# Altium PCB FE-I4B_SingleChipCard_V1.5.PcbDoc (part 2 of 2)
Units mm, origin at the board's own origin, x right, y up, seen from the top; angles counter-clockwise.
Board outline 100 x 100 mm, 5 copper layers (Top Layer, pad layer, GND, power, Bottom Layer); 136 components, 118 nets, 544 pads, 176 vias.
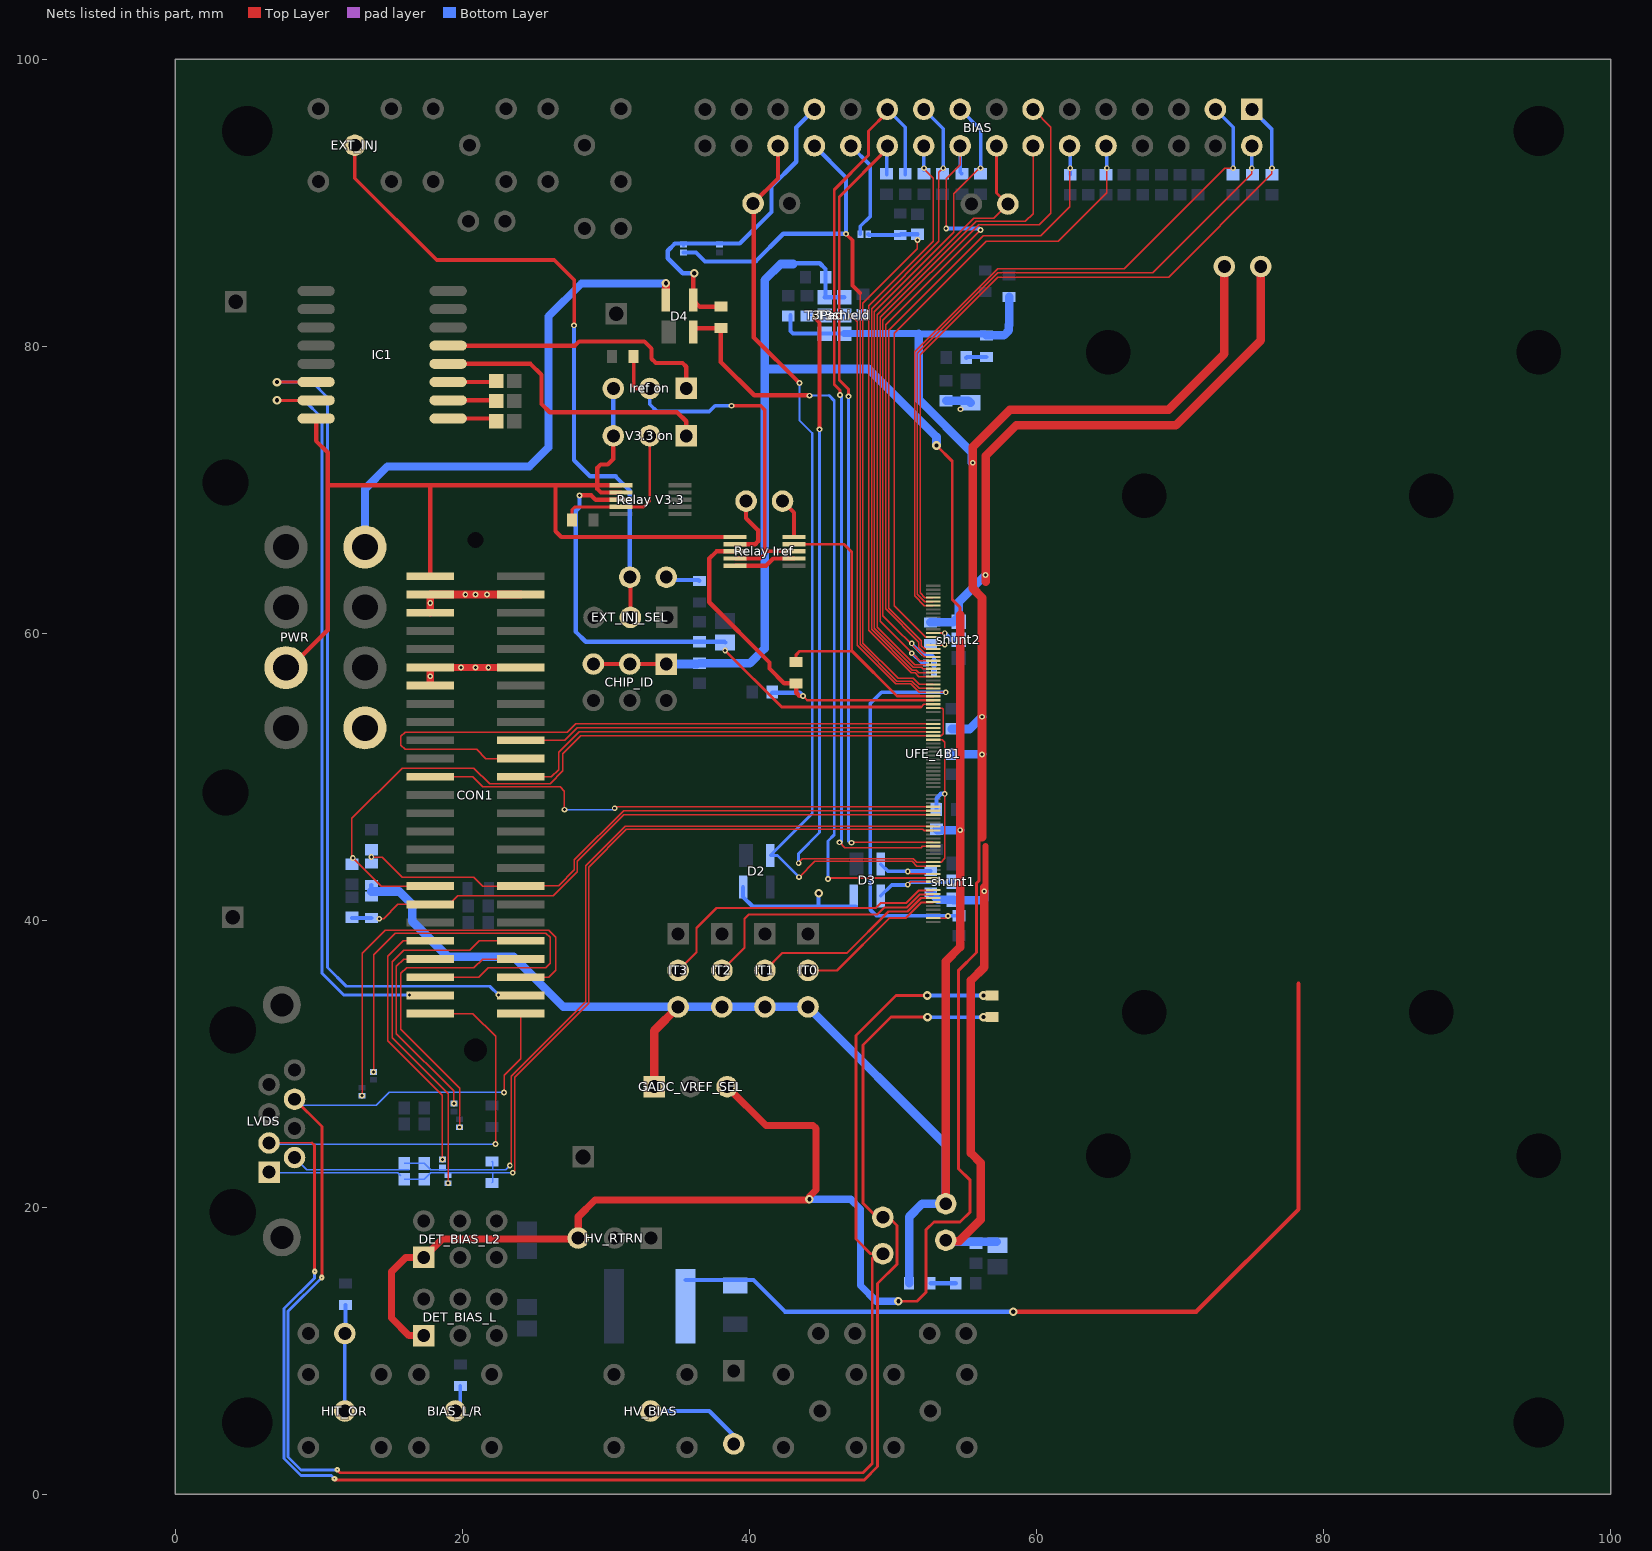
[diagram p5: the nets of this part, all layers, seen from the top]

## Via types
v1: diameter 0.4, hole 0.2, Top Layer to Bottom Layer, 157 vias
v2: diameter 0.6, hole 0.3, Top Layer to Bottom Layer, 13 vias
v3: diameter 0.4, hole 0.102, Top Layer to Bottom Layer, 4 vias
v4: diameter 0.25, hole 0, Top Layer to Bottom Layer, 2 vias

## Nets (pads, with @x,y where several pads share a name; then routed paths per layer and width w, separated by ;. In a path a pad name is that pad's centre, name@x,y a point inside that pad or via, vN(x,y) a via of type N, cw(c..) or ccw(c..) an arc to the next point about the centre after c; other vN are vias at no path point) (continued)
IREFEN: "Iref on.2" "Relay Iref.4" "Relay Iref.8" R22.2 | length 27.1
  Top Layer w0.254: R22.2@31.925,79.275 31.925,77.2 32.075,77.05 33.05,77.05 ; v1(38.75,75.85) 40.775,75.85 41.05,75.575 41.05,65.7 ; 39,65.2 40.75,65.2 41.05,65.5 41.05,65.7 ; 43.1,65.7 41.05,65.7
  Bottom Layer w0.254: 33.05,77.05 33.05,75.95 33.55,75.45 37.2,75.45 37.6,75.85 v1(38.75,75.85)
IREFON: "Iref on.1" IC1.5 | length 19.4
  Top Layer w0.3: IC1.5@19,80.035 27.835,80.035 28.125,80.325 32.675,80.325 33.175,79.825 33.175,79.125 33.475,78.825 35.325,78.825 35.59,78.56 35.59,77.05
IREFOUT: "Relay Iref.9" sj3.1 UFE_4B1.29 | length 22.6
  Top Layer w0.15: 51.8,55.6 UFE_4B1.29@52.8,55.6
  Top Layer w0.2: 43.1,66.2 46.575,66.2 47.125,65.65 47.125,58.775 50.275,55.625 51.825,55.625 ; sj3.1@43.25,58 43.25,58.5 43.49,58.74 43.735,58.74 47.11,58.74
IREFTUNE0: IT0.2 UFE_4B1.125 | length 10.7
  Top Layer w0.15: IT0.2@44.075,36.5 46.1,36.5 49.76,40.16 50.902,40.16 51.982,41.24 52.765,41.24 UFE_4B1.125@52.8,41.275
IREFTUNE1: IT1.2 UFE_4B1.124 | length 13.8
  Top Layer w0.15: IT1.2@41.075,36.5 42.3,37.725 46.8,37.725 49.685,40.61 51.013,40.61 51.953,41.55 UFE_4B1.124@52.8,41.55
IREFTUNE2: IT2.2 UFE_4B1.123 | length 18.1
  Top Layer w0.15: IT2.2@38.075,36.5 39.65,38.075 39.65,40.1 39.95,40.4 48.9,40.4 49.387,40.888 50.951,40.888 51.854,41.79 52.765,41.79 UFE_4B1.123@52.8,41.825
IREFTUNE3: IT3.2 UFE_4B1.122 | length 21.1
  Top Layer w0.15: IT3.2@35.025,36.5 36.3,37.775 36.3,39.45 37.7,40.85 48.8,40.85 49.15,41.2 50.924,41.2 51.789,42.065 52.765,42.065 UFE_4B1.122@52.8,42.1
LVDSDRVIREF: BIAS.19 C42.1 UFE_4B1.17 | length 44.5
  Top Layer w0.1: UFE_4B1.17@52.8,57.25 51.8,57.25 51.63,57.42 51.342,57.42 48.5,60.262 48.5,82.6 53.2,87.3 53.2,92.1 v1(53.5,92.4)
  Bottom Layer w0.25: BIAS.19@52.14,96.5 53.5,95.14 C42.1@53.5,92.3
LVDSDRVVOS: BIAS.20 C57.1 UFE_4B1.18 | length 42
  Top Layer w0.1: v1(52.15,92.4) 52.15,92.35 52.8,91.7 52.8,87.3 48.3,82.8 48.3,60.194 51.264,57.23 51.551,57.23 51.806,56.975 UFE_4B1.18@52.8,56.975
  Bottom Layer w0.25: BIAS.20@52.14,93.96 52.15,93.95 52.15,92.25 52.2,92.3 C57.1@52.15,92.35
LVDSRECVBN: BIAS.22 C59.1 UFE_4B1.94 | length 57.9
  Top Layer w0.1: v1(47.1,45.4) 47.125,45.425 UFE_4B1.94@52.8,45.425 ; BIAS.22@49.6,93.75 BIAS.22@49.6,93.96
  Top Layer w0.2: v1(46.9,76.5) 46.9,77 46.25,77.65 46.25,90.4 BIAS.22@49.6,93.75
  Bottom Layer w0.2: 46.9,45.5 v1(46.9,76.5)
  Bottom Layer w0.25: C59.1@49.55,91.95 49.55,93.91 BIAS.22@49.6,93.96
LVDSRECVBP: BIAS.21 C44.1 UFE_4B1.95 | length 64.7
  Top Layer w0.1: v1(46.275,45.425) 46.635,45.065 46.954,45.065 46.959,45.06 47.241,45.06 47.246,45.065 51.965,45.065 52.05,45.15 UFE_4B1.95@52.8,45.15 ; BIAS.21@49.6,96.3 BIAS.21@49.6,96.5
  Top Layer w0.2: v1(46.3,76.6) 46.3,76.925 45.9,77.325 45.9,90.9 48.3,93.3 48.3,95 BIAS.21@49.6,96.3
  Bottom Layer w0.2: v1(46.275,45.425) 46.325,45.425 46.4,45.5 46.4,76.5 v1(46.3,76.6)
  Bottom Layer w0.25: BIAS.21@49.6,96.5 50.85,95.25 C44.1@50.85,91.95
NC1: "Relay Iref.5" "Relay Iref.7" | length 4.3
  Top Layer w0.3: 39,64.7 41.15,64.7 41.65,65.2 43.1,65.2
NetBIAS_L/R_1: BIAS_L/R.1 R1.1 | length 1.9
  Bottom Layer w0.254: BIAS_L/R.1@19.5,5.8 19.85,6.15 R1.1@19.85,7.55
NetCON1_41: CON1.41 JP2.2 | length 19.1
  Top Layer w0.1: CON1.41@17.75,38.565 15.865,38.565 14.8,37.5 14.8,31.6 18.6,27.8 v1(18.6,23.325)
NetCON1_42: CON1.42 JP1.2 | length 26.6
  Top Layer w0.1: v1(19,21.675) 19,27.9 15.1,31.8 15.1,37.1 15.9,37.9 20.5,37.9 21.165,38.565 CON1.42@24.05,38.565
NetCON1_43: CON1.43 JP4.2 | length 13.9
  Top Layer w0.1: CON1.43@17.75,37.295 15.895,37.295 15.4,36.8 15.4,32.1 19.4,28.1 19.4,27.3 v1@19.3,27.2
  other v1: 19.4,27.225
NetCON1_44: CON1.44 JP3.2 | length 21.2
  Top Layer w0.1: v1@19.7,25.575 19.8,25.675 19.8,28.3 15.7,32.4 15.7,36.3 16.1,36.7 20.8,36.7 21.395,37.295 CON1.44@24.05,37.295
  other v1: 19.8,25.575
NetCON1_45: CON1.45 JP6.2 | length 31.8
  Top Layer w0.1: v1(13.8,29.425) 13.8,37.6 15.3,39.1 25.8,39.1 26.1,38.8 26.1,37 25.8,36.7 21.8,36.7 21.125,36.025 CON1.45@17.75,36.025
NetCON1_46: CON1.46 JP5.2 | length 29.2
  Top Layer w0.1: v1(13,27.775) 13,37.7 14.6,39.3 26,39.3 26.5,38.8 26.5,36.5 26.025,36.025 CON1.46@24.05,36.025
NetCR1_1: CR1.1 RR1.1 | length 1.8
  Bottom Layer w0.3: RR1.1@52.625,14.7 CR1.1@54.375,14.7
NetCR2_1: CR2.1 RR2.1 | length 1.4
  Bottom Layer w0.3: CR2.1@55.1,79.2 55.15,79.25 RR2.1@56.5,79.25
NetEXT_INJ_1: EXT_INJ.1 EXT_INJ_SEL.2 JPterm.2 | length 46.5
  Top Layer w0.254: EXT_INJ.1@12.5,94 12.5,91.7 18.2,86 26.4,86 27.775,84.625 v1(27.775,81.45)
  Top Layer w0.3: JPterm.2@31.66,63.7 31.7,63.66 EXT_INJ_SEL.2@31.7,61.1
  Bottom Layer w0.3: v1@27.775,81.475 v1(27.775,81.45) 27.775,72.05 28.9,70.925 30.67,70.925 31.66,69.935 JPterm.2@31.66,63.9
NetHIT_OR_1: HIT_OR.1 HitOr.1 R11.1 | length 7.4
  Top Layer w0.254: HitOr.1@11.8,11.2 HitOr.1@11.85,11.25
  Bottom Layer w0.254: HIT_OR.1@11.8,5.8 HitOr.1@11.8,11.2 ; HitOr.1@11.85,11.25 R11.1@11.85,13.2
NetHV_BIAS_1: HV_BIAS.1 sHV.3 | length 7.8
  Bottom Layer w0.3: HV_BIAS.1@33.1,5.8 37.2,5.8 sHV.3@38.9,4.1 ; sHV.3@38.9,4.1 39,4 39,3.61 sHV.3@38.9,3.51 sHV.3@38.9,4.1
NetIC1_1: IC1.1 P1.2 | length 3.4
  Top Layer w0.3: IC1.1@19,74.955 22.179,74.955 P1.2@22.361,74.773
NetIC1_2: IC1.2 P2.2 | length 3.4
  Top Layer w0.3: IC1.2@19,76.225 22.309,76.225 P2.2@22.361,76.173
NetIC1_3: IC1.3 P3.2 | length 3.4
  Top Layer w0.3: IC1.3@19,77.495 22.283,77.495 P3.2@22.361,77.573
NetIref_1: "Relay Iref.10" Iref.1 | length 2.8
  Top Layer w0.3: Iref.1@42.3,69.2 43.1,68.4 43.1,66.7
NetIref_2: "Relay Iref.2" Iref.2 | length 4.8
  Top Layer w0.3: 39,66.2 40.4,66.2 40.6,66.4 40.6,67.17 39.76,68.01 Iref.2@39.76,69.2
NetJPterm_1: JPterm.1 R5.2 | length 2.4
  Bottom Layer w0.1: R5.2@36.45,63.7 R5.2@36.5,63.65
  Bottom Layer w0.3: JPterm.1@34.2,63.7 36.45,63.7 R5.2@36.5,63.65
NetR21_2: "Relay V3.3.4" "V3.3 on.2" R21.2 | length 10.9
  Top Layer w0.2: R21.2@27.625,67.875 27.625,68.6 27.825,68.8 31.05,68.8 32.625,68.8 33.05,69.225 33.05,73.75
NTC1: CON1.49 EXT_NTC.1 LVDS.3 NTC.2 | length 137.4
  Top Layer w0.1: LVDS.3@6.52,24.476 9.524,24.476 ; CON1.49@17.75,33.485 20.715,33.485 22.3,31.9 v1(22.3,24.4)
  Top Layer w0.2: 9.524,24.476 9.7,24.3 v3(9.7,15.525) ; v3@11.075,1 48,1 48.925,1.925 48.925,14.675 50.275,16.025 50.275,18.725 49.7,19.3 48.875,19.3 47.9,20.275 47.9,31.3 49.85,33.25 v2(52.4,33.25)
  Bottom Layer w0.1: LVDS.3@6.52,24.476 6.596,24.4 v1(22.3,24.4)
  Bottom Layer w0.2: v3(9.7,15.525) 9.7,15.075 7.56,12.935 7.56,2.48 8.74,1.3 10.85,1.3 v3(11.075,1.075)
  Bottom Layer w0.25: v2(52.4,33.25) v2(56.3,33.25)
NTC2: CON1.50 EXT_NTC.2 LVDS.6 NTC.1 | length 130.1
  Top Layer w0.1: v1(22.9,28) 22.9,29.2 24.05,30.35 CON1.50@24.05,33.485
  Top Layer w0.2: LVDS.6@8.298,27.524 10.2,25.622 v3(10.2,15.1) ; v3(11.275,1.7) 11.475,1.5 47.9,1.5 48.55,2.15 48.55,16.435 48.875,16.76 48.44,16.76 47.425,17.775 47.425,31.975 50.2,34.75 v2(52.375,34.75)
  Bottom Layer w0.1: LVDS.6@8.298,27.524 8.722,27.1 14,27.1 14.9,28 v1(22.9,28)
  Bottom Layer w0.2: v3(10.2,15.1) 7.85,12.75 7.85,2.6 8.75,1.7 v3(11.275,1.7)
  Bottom Layer w0.25: v2(52.375,34.75) v2(56.3,34.75)
PLLIBIAS: BIAS.18 C41.1 UFE_4B1.14 | length 44.7
  Top Layer w0.1: UFE_4B1.14@52.8,58.625 52.175,58.625 51.785,59.015 51.785,59.378 49.513,61.65 49.5,61.65 49.5,81.5 v1(56.1,88.1) ; v1(53.7,88.2) 53.7,91.65 54.68,92.63 BIAS.18@54.68,93.96
  pad layer w0.1: v1(53.7,88.2) v1@53.8,88.1
  Bottom Layer w0.25: v1(53.7,88.2) 56,88.2 v1(56.1,88.1) ; BIAS.18@54.68,93.96 54.68,92.12 C41.1@54.8,92
PLLICP: BIAS.17 C56.1 UFE_4B1.16 | length 45.2
  Top Layer w0.1: UFE_4B1.16@52.8,57.525 52.075,57.525 51.99,57.61 51.421,57.61 48.7,60.331 48.7,82.4 54.225,87.925 54.225,90.625 v1@56.1,92.5
  Bottom Layer w0.25: BIAS.17@54.68,96.5 56.1,95.08 v1(56.1,92.4)
PRMPVBNFOL: BIAS.3 C49.1 UFE_4B1.4 | length 50.7
  Top Layer w0.1: UFE_4B1.4@52.8,61.925 52.175,61.925 51.5,62.6 51.5,79.6 57.3,85.4 66.1,85.4 73.1,92.4 v1(73.7,92.4)
  Bottom Layer w0.25: BIAS.3@72.46,96.5 73.7,95.26 v1(73.7,92.4)
PRMPVBNLCC: BIAS.2 C34.1 UFE_4B1.3 | length 48.5
  Top Layer w0.1: UFE_4B1.3@52.8,62.2 52.2,62.2 51.7,62.7 51.7,79.5 57.3,85.1 68.1,85.1 75,92 v1(75,92.4)
  Bottom Layer w0.25: v1(75,92.4) BIAS.2@75,93.96
PRMPVBP: BIAS.12 C35.1 UFE_4B1.13 | length 44.6
  Top Layer w0.1: UFE_4B1.13@52.8,58.9 52.2,58.9 51.975,59.125 51.975,59.456 49.7,61.731 49.7,81.1 51.7,83.1 56.3,87.7 60.3,87.7 62.3,89.7 v1@62.3,92.3 ; BIAS.12@62.3,93.96 BIAS.12@62.35,93.91
  Bottom Layer w0.25: C35.1@62.35,91.95 BIAS.12@62.35,93.91
  other v1: 62.35,92.4
PRMPVBPF: BIAS.1 C48.1 UFE_4B1.2 | length 52.4
  Top Layer w0.1: UFE_4B1.2@52.8,62.475 52.225,62.475 51.9,62.8 51.9,79.4 57.3,84.8 69.2,84.8 76.4,92 v1(76.4,92.4)
  Bottom Layer w0.25: BIAS.1@75,96.5 76.4,95.1 v1(76.4,92.4)
RABAR1: C46.1 CON1.35 UFE_4B1.41 UFE_4B1.52 | length 56.7
  Top Layer w0.1: CON1.35@17.75,42.375 14.325,42.375 v1(12.359,44.341) 12.3,44.4 12.3,47.1 15.8,50.6 20.8,50.6 21.9,49.5 26.1,49.5 27,50.4 27,51.6 28.25,52.85 UFE_4B1.52@52.8,52.85 53.35,52.85 53.5,53 53.5,54.7 53.425,54.775 UFE_4B1.41@52.8,54.775
RD1BAR: C45.1 CON1.36 R12.1 UFE_4B1.84 | length 42.6
  Top Layer w0.1: v1(13.65,44.4) 14.4,44.4 15.8,43 20.8,43 21.425,42.375 CON1.36@24.05,42.375 24.05,42.4 26.7,42.4 27.8,43.5 27.8,44.2 31.225,47.625 UFE_4B1.84@52.8,47.625
RD2BAR: CD45.1 CON1.37 RD12.1 UFE_4B1.85 | length 43.4
  Top Layer w0.1: v1(14.2,40.1) 14.5,40.1 15.505,41.105 CON1.37@17.75,41.105 19.08,41.105 19.675,41.7 26.325,41.7 28,43.375 28,44.1 31.25,47.35 UFE_4B1.85@52.8,47.35
  Bottom Layer w0.3: CD45.1@12.3,40.15 RD12.1@13.65,40.15
REFCLKN: C6.1 C6.2 JP2.1 LVDS.2 R9.2 UFE_4B1.88 | length 65.1
  Top Layer w0.1: v1@23.4,23 23.4,29.125 28.6,34.325 28.6,43.8 31.35,46.55 UFE_4B1.88@52.775,46.55
  Top Layer w0.12: v1(23.3,22.9) v1@23.4,23 ; UFE_4B1.88@52.775,46.55 UFE_4B1.88@52.8,46.525
  Bottom Layer w0.1: LVDS.2@8.298,23.46 9.158,22.6 16.3,22.6 ; C6.2@15.95,23.05 C6.1@17.35,23.05 17.8,22.6 22.1,22.6 ; R9.2@22.05,23.2 22.1,23.15 22.1,22.6 ; v1(23.3,22.9) 23,22.6 22.1,22.6
REFCLKP: C7.1 C7.2 JP1.1 LVDS.1 R9.1 UFE_4B1.89 | length 66.3
  Top Layer w0.1: 23.65,22.55 23.65,29.05 28.8,34.2 28.8,43.7 31.425,46.325 52.075,46.325 52.1,46.3
  Top Layer w0.12: v1(23.5,22.4) 23.65,22.55 ; 52.1,46.3 52.15,46.25 UFE_4B1.89@52.8,46.25
  Bottom Layer w0.1: LVDS.1@6.52,22.4 15.5,22.4 C7.1@15.7,22.2 ; C7.1@15.95,21.95 C7.2@17.35,21.95 17.8,22.4 22.1,22.4 ; R9.1@22.05,21.7 22.1,21.75 22.1,22.4 ; v1(23.5,22.4) 22.1,22.4
REG1IN: C19.1 C20.1 CON1.3 CON1.4 CON1.5 D2.4 D3.4 D4.4 Digital.1 PWR.7 Rext1.1 shunt1.1 | length 92.9
  Top Layer w0.4: v1@56.45,42.1 56.45,45.175
  Top Layer w0.55: CON1.5@17.75,61.425 CON1.3@17.75,62.695 v1(20.2,62.695) v1(20.9,62.695) v1(21.7,62.695) CON1.4@24.05,62.695 ; D4.4@34.175,83.2 v2(34.175,84.375)
  Top Layer w0.6: Digital.1@53.65,17.625 54.6,17.625 56.1,19.125 56.1,23.1 55.425,23.775 55.425,35.8 56.35,36.725 56.35,42.3
  Bottom Layer w0.3: D2.4@39.55,42.3 39.55,41.625 40.225,40.95 44.8,40.95 ; v2(44.825,41.875) 44.8,41.85 44.8,40.95 ; D3.4@47.4,40.95 44.8,40.95
  Bottom Layer w0.55: PWR.7@13.2,66 13.2,70.05 14.775,71.625 24.675,71.625 26,72.95 26,82.075 28.3,84.375 v2(34.175,84.375)
  Bottom Layer w0.6: Rext1.1@52.625,41.925 53.125,41.425 shunt1.1@54.225,41.425 ; Digital.1@53.675,17.7 53.775,17.6 C19.1@57.225,17.6 ; shunt1.1@54.2,41.4 56.35,41.4 56.35,42.011 v1(56.352,42.013)
  other v1: 17.75,62.1
REG1OUT: C26.1 C27.1 C28.1 CHIP_ID.1 CHIP_ID.3 CHIP_ID.5 Digital.2 GADC_VREF_SEL.1 IT0.3 IT1.3 IT2.3 IT3.3 R12.2 RD12.2 RR1.2 T3Pad.3 T3shield.3 | length 182.3
  Top Layer w0.2: v2(53.025,73.075) 54.125,71.975 54.125,62.35 54.675,61.8 54.675,61.275
  Top Layer w0.3: CHIP_ID.5@29.12,57.85 CHIP_ID.3@31.66,57.85 CHIP_ID.1@34.2,57.85
  Top Layer w0.6: GADC_VREF_SEL.1@33.36,28.4 33.36,32.295 IT3.3@35.025,33.96 ; Digital.2@53.675,20.24 53.675,37.125 54.675,38.125 v1(54.675,46.275) 54.675,61.275
  Bottom Layer w0.2: T3Pad.3@45.25,83.405 T3Pad.3@45.3,83.455
  Bottom Layer w0.3: RD12.2@13.65,42 R12.2@13.65,42.45 ; 43.225,85.775 44.9,85.775 45.3,85.375 C27.1@45.3,84.8 T3Pad.3@45.3,83.455 ; T3Pad.3@45.25,83.405 T3shield.3@46.6,83.405
  Bottom Layer w0.6: RD12.2@13.65,42 15.6,42 16.5,41.1 16.5,39.925 18.975,37.45 23.55,37.45 27.04,33.96 IT3.3@35.025,33.96 IT2.3@38.075,33.96 IT1.3@41.075,33.96 IT0.3@44.075,33.96 53.675,24.36 Digital.2@53.675,20.24 52.025,20.24 51.125,19.34 RR1.2@51.125,14.7 ; CHIP_ID.1@34.2,57.85 C28.1@36.322,57.85 ; C28.1@36.5,57.9 40.025,57.9 41.05,58.925 41.05,78.404 ; 43.05,85.725 42.175,85.725 41.05,84.6 41.05,78.404 ; v2@53.025,73.175 53.025,73.675 48.296,78.404 41.05,78.404 ; C26.1@53.05,46.325 53.1,46.275 v1(54.675,46.275)
REG2IN: Analog.1 C17.1 C18.1 CON1.11 CON1.12 CON1.13 PWR.1 Rext2.1 shunt2.1 | length 52
  Top Layer w0.5: CON1.13@17.75,56.345 CON1.11@17.75,57.615 CON1.12@24.05,57.615
  Top Layer w0.6: 56.45,63.575 v1(56.45,64.05) 56.45,72.35 58.575,74.475 69.7,74.475 75.625,80.4 Analog.1@75.625,85.55 Analog.1@75.413,85.338
  Bottom Layer w0.6: Rext2.1@52.6,60.75 54.2,60.75 shunt2.1@54.412,60.962 ; C18.1@53.7,76.2 55.25,76.2 C17.1@55.4,76.05 ; shunt2.1@54.575,60.8 54.575,62.175 v1(56.45,64.05)
  other v1: 17.75,57 19.9,57.615 20.9,57.615 21.8,57.615 54.7,75.6
REG2OUT: Analog.2 C31.1 C32.1 C33.1 DET_BIAS_L2.1 DET_BIAS_L.1 GADC_VREF_SEL.3 HV_RTRN.3 R2.2 RR2.2 T3Pad.1 T3shield.1 | length 188.2
  Top Layer w0.2: v2(50.375,13.45) 51.675,13.45 52.303,14.078 52.303,18.428 52.85,18.975 54.675,18.975 55.375,19.675 55.375,21.875 54.55,22.7 54.55,36.475 55.825,37.75 55.825,42.575 56,42.75 56,46.254
  Top Layer w0.5: DET_BIAS_L.1@17.3,11.05 16.275,11.05 15.05,12.275 15.05,15.5 16.05,16.5 DET_BIAS_L2.1@17.3,16.5 18.575,17.775 27.985,17.775 HV_RTRN.3@28.06,17.85 28.06,19.335 29.225,20.5 44.125,20.5 v2(44.175,20.55) ; GADC_VREF_SEL.3@38.44,28.4 41.145,25.695 44.433,25.695 44.632,25.496 44.632,21.208 v2@44.175,20.751
  Top Layer w0.6: 56.2,45.8 v1(56.2,51.55) v1(56.2,54.175) 56.2,62.475 55.55,63.125 v1(55.55,71.875) 55.55,72.975 58.15,75.575 69.2,75.575 73.085,79.46 Analog.2@73.085,85.55
  Bottom Layer w0.3: C33.1@42.85,82.15 42.85,81.05 43.025,80.875 T3Pad.1@45.25,80.875 T3shield.1@46.6,80.875
  Bottom Layer w0.5: v2(44.175,20.55) 47.05,20.55 47.725,19.875 47.725,14.55 48.825,13.45 v2(50.375,13.45) ; T3shield.1@46.6,80.875 51.825,80.875 ; 51.8,80.85 56.4,80.85 RR2.2@56.5,80.75 ; 58.075,81.475 58.1,81.45
  Bottom Layer w0.6: 51.8,80.85 51.8,76.275 55.5,72.575 v1@55.5,71.875 ; C31.1@54.1,53.325 55.35,53.325 v1(56.2,54.175) v1@56.175,54.2 ; C32.1@54.125,51.575 54.15,51.55 v1(56.2,51.55) ; RR2.2@56.5,80.75 57.725,80.75 58.075,81.1 58.075,81.475 ; 58.1,81.45 R2.2@58.1,83.45
REGABDACLD: CON1.20 UFE_4B1.48 | length 29.1
  Top Layer w0.1: CON1.20@24.05,52.535 27.135,52.535 28,53.4 UFE_4B1.48@52.8,53.4
REGABSTBLD: CON1.22 UFE_4B1.47 | length 46.9
  Top Layer w0.1: CON1.22@24.05,51.15 CON1.22@24.05,51.265 21.635,51.265 21,51.9 16,51.9 15.7,52.2 15.7,52.8 16,53.1 27.3,53.1 27.875,53.675 UFE_4B1.47@52.8,53.675
REXT1: D3.2 Rext1.2 UFE_4B1.116 | length 5.5
  Top Layer w0.1: v1(51.025,43.4) 51.2,43.225 UFE_4B1.116@52.8,43.225
  Bottom Layer w0.25: D3.2@49.15,43.9 49.65,43.4 v1(51.025,43.4) 51.05,43.425 Rext1.2@52.625,43.425
REXT2: Rext2.2 UFE_4B1.7b | length 1.7
  Top Layer w0.1: UFE_4B1.7b@52.8,59.175 53.5,59.175 v1@53.5,59.2
  Bottom Layer w0.1: Rext2.2@52.6,59.25 52.65,59.2 v1(53.6,59.2)
SCL: CON1.48 IC1.14 | length 59.2
  Top Layer w0.2: v2(7.075,77.495) IC1.14@9.8,77.495 ; IC1.14@10.6,77.5 10.69,77.5 IC1.14@10.695,77.495
  Bottom Layer w0.2: v2(7.075,77.495) 9.53,77.495 10.6,76.425 10.6,36.7 11.9,35.4 21.9,35.4 v1(22.5,34.8)
SDA: CON1.47 IC1.15 | length 51.8
  Top Layer w0.2: v2(7.075,76.225) IC1.15@9.8,76.225
  Bottom Layer w0.2: v2(7.075,76.225) 8.975,76.225 10.2,75 10.2,36.3 11.7,34.8 v1(16.3,34.8)
SELALTBUS: CON1.24 UFE_4B1.49 | length 30.7
  Top Layer w0.1: CON1.24@24.05,49.995 26.195,49.995 26.7,50.5 26.7,51.7 28.125,53.125 UFE_4B1.49@52.8,53.125
SELCMD: CON1.23 UFE_4B1.81 | length 36.7
  Top Layer w0.1: CON1.23@17.75,49.995 20.705,49.995 21.4,49.3 26.8,49.3 27.1,49 v1@27.1,47.8 ; v1(30.6,47.8) 30.7,47.9 UFE_4B1.81@52.8,47.9
  Bottom Layer w0.1: v1(27.1,47.7) 30.5,47.7 v1(30.6,47.8)
SENSOR: C3.1 R3.2 | length 62.3
  Top Layer w0.3: v2(58.375,12.725) 71.125,12.725 78.25,19.85 78.25,35.575
  Bottom Layer w0.3: C3.1@35.55,14.925 40.275,14.925 42.475,12.725 v2(58.375,12.725)
TDACVBP: BIAS.10 C38.1 UFE_4B1.11 | length 44.6
  Top Layer w0.1: UFE_4B1.11@52.8,59.725 52.275,59.725 50.1,61.9 50.1,80.9 56.5,87.3 61.5,87.3 64.9,90.7 v1@64.9,92.3
  Bottom Layer w0.25: BIAS.10@64.84,93.96 64.9,93.9 v1(64.9,92.4)
V3.3IN: "Iref on.3" "Relay Iref.1" "Relay V3.3.1" "Relay V3.3.2" "V3.3 on.3" CON1.1 IC1.16 PWR.4 | length 71.2
  Top Layer w0.3: PWR.4@7.7,57.6 8,57.6 10.6,60.2 10.6,70.3 ; IC1.16@9.8,74.955 9.8,73.4 10.6,72.6 10.6,70.3 ; CON1.1@17.75,63.965 17.75,70.25 ; 26.475,70.3 26.475,67.1 26.875,66.7 39,66.7 ; 30.51,73.75 30.51,72.135 30.125,71.75 29.625,71.75 29.4,71.525 29.4,70.3 ; 31.05,69.8 29.65,69.8 29.4,70.05 29.4,70.3 ; 31.05,70.3 29.4,70.3 ; 10.6,70.3 29.4,70.3
  Bottom Layer w0.3: 30.51,73.75 30.51,77.05
V3.3ON: "V3.3 on.1" IC1.4 | length 20.4
  Top Layer w0.3: IC1.4@19,78.765 24.735,78.765 25.5,78 25.5,75.975 26.075,75.4 34.95,75.4 35.59,74.76 35.59,73.75
VBBNIN: "Relay Iref.3" C43.1 sj3.2 UFE_4B1.30 | length 26.4
  Top Layer w0.15: v1(43.725,55.625) 44.025,55.325 UFE_4B1.30@52.8,55.325
  Top Layer w0.3: 39,65.7 37.7,65.7 37.2,65.2 37.2,62.15 41.388,57.962 41.388,57.537 42.425,56.5 sj3.2@43.25,56.5 43.25,55.85 43.475,55.625 v1(43.725,55.625)
  Bottom Layer w0.3: C43.1@41.575,55.85 43.5,55.85 v1(43.725,55.625)
VBP1: BIAS.28 D2.2 mreg1.1 UFE_4B1.114 | length 65.8
  Top Layer w0.1: v1(43.45,43) 44.55,44.1 51.329,44.1 51.654,43.775 UFE_4B1.114@52.8,43.775
  Top Layer w0.15: mreg1.1@40.05,89.975 mreg1.1@40.3,89.725
  Top Layer w0.3: mreg1.1@40.25,89.95 41.98,91.68 BIAS.28@41.98,93.96 ; mreg1.1@40.3,89.725 40.3,80.6 v1(43.475,77.425)
  Bottom Layer w0.15: v1(43.475,77.425) 43.475,74.825 44.375,73.925
  Bottom Layer w0.2: v1(43.45,43) 41.95,44.5 D2.2@41.45,44.5 44.375,47.425 44.375,73.925
VBP2: BIAS.16 mreg2.1 UFE_4B1.9b | length 43.4
  Top Layer w0.1: UFE_4B1.9b@52.8,57.8 51.5,57.8 48.9,60.4 48.9,82.2 55.625,88.925 57.025,88.925 mreg2.1@58,89.9
  Top Layer w0.2: BIAS.16@57.22,93.96 57.22,90.68 mreg2.1@58,89.9
VDD33: "Relay V3.3.3" C13.1 C14.1 UFE_4B1.37 | length 39.6
  Top Layer w0.1: 51.95,54.85 52.15,55.05 UFE_4B1.37@52.8,55.05
  Top Layer w0.2: v1(38.3,58.8) 42.25,54.85 51.95,54.85
  Top Layer w0.3: v1(28.15,69.6) 28.975,69.6 29.275,69.3 31.05,69.3
  Bottom Layer w0.3: v1(28.15,69.6) 28.15,68.775 27.9,68.525 27.9,60.09 28.59,59.4 C13.1@36.5,59.4 38.25,59.4 C14.1@38.3,59.35
VDDDSHUNT1: D3.3 shunt1.2 UFE_4B1.118 | length 7.3
  Top Layer w0.1: v1(51.025,42.475) 51.225,42.675 UFE_4B1.118@52.8,42.675
  Bottom Layer w0.25: D3.3@49.15,41.7 49.9,42.45 51,42.45 v1(51.025,42.475) 51.2,42.65 54.19,42.65 shunt1.2@54.225,42.685
VDDDSHUNT2: shunt2.2 UFE_4B1.6b | length 1.9
  Top Layer w0.15: UFE_4B1.6b@52.8,60 v1@53.5,60
  Bottom Layer w0.3: v1(53.6,60) 54.06,59.54 shunt2.2@54.575,59.54
VDDT3PAD: C9.1 C10.1 T3Pad.2 UFE_4B1.59 UFE_4B1.105 | length 61
  Top Layer w0.1: v1@43.425,44.05 43.665,44.29 51.408,44.29 51.648,44.05 UFE_4B1.105@52.8,44.05 53.35,44.05 53.6,44.3 v1@53.6,48.802 ; UFE_4B1.59@52.8,52.575 53.425,52.575 53.6,52.4 v1@53.6,48.802 ; v1@53.575,48.8 53.577,48.802 v1@53.6,48.802 ; v1(53.603,48.802) v1@53.6,48.802
  Top Layer w0.25: v1(44.6,82.135) 44.6,81.9 44.875,81.625 v1(44.875,74.2)
  Bottom Layer w0.1: C9.1@44.015,82.135 T3Pad.2@45.25,82.135
  Bottom Layer w0.2: v1(43.425,43.975) 43.425,44.65 44.875,46.1 v1@44.875,74.1
  Bottom Layer w0.3: C10.1@53.025,47.725 53.025,48.5 53.327,48.802 v1(53.603,48.802)
VDDT3SHIELD: C11.1 C12.1 T3shield.2 UFE_4B1.28 UFE_4B1.134 | length 59.8
  Top Layer w0.1: v1(47.1,82.1) 47.5,81.7 47.5,59.163 50.193,56.47 51.237,56.47 51.832,55.875 v1(53.675,55.875) ; UFE_4B1.134@52.8,40.15 53.675,40.15 v1(53.825,40.3)
  Bottom Layer w0.1: T3shield.2@46.635,82.1 v1(47.1,82.1) ; C12.1@47.835,82.135 C12.1@47.9,82.2
  Bottom Layer w0.25: v1(53.675,55.875) 49.2,55.875 48.4,55.075 48.4,40.75 48.85,40.3 v1(53.825,40.3) 54.575,40.3 C11.1@54.6,40.325
  Bottom Layer w0.3: T3shield.2@46.6,82.135 C12.1@47.835,82.135
VREF1: D4.2 Resd.1 UFE_4B1.117 | length 54.3
  Top Layer w0.1: v1@45.475,42.85 v1@45.575,42.95
  Top Layer w0.15: v1@45.575,42.95 UFE_4B1.117@52.8,42.95
  Top Layer w0.3: D4.2@36.075,81 36.325,81.25 Resd.1@38.025,81.25 ; Resd.1@38,81.25 38,78.9 40.325,76.575 44.175,76.575 v1(44.175,76.55)
  Bottom Layer w0.15: v1(44.175,76.55) 45.55,76.55
  Bottom Layer w0.2: v1(45.475,42.875) 45.475,45.525 45.9,45.95 45.9,76.2 45.55,76.55
VREF1_IN: BIAS.25 D4.3 Resd.2 sj21.1 sj115.1 | length 25.1
  Top Layer w0.1: BIAS.25@44.52,96.5 BIAS.25@44.9,96.5
  Top Layer w0.3: v2(36.15,85.075) 36.075,85 D4.3@36.075,83.2 36.525,82.75 Resd.2@38.025,82.75 ; Resd.2@38,82.75 Resd.2@38.025,82.775
  Bottom Layer w0.1: BIAS.25@44.52,96.08 BIAS.25@44.52,96.5 ; BIAS.25@44.7,96.5 BIAS.25@44.52,96.5 ; BIAS.25@44.9,96.5 BIAS.25@44.52,96.5
  Bottom Layer w0.3: sj21.1@35.4,87.075 sj21.1@35.325,87.15 ; v2(36.15,85.075) 35.35,85.075 34.3,86.125 34.3,86.65 34.8,87.15 sj21.1@35.325,87.15 ; BIAS.25@44.52,96.5 43.25,95.23 43.25,92.85 41.525,91.125 41.525,89.35 39.325,87.15 sj21.1@35.325,87.15
VREF2: BIAS.13 sj15.1 sj19.1 UFE_4B1.8b | length 50.8
  Top Layer w0.1: UFE_4B1.8b@52.8,58.35 52.175,58.35 49.3,61.225 49.3,81.8 55.975,88.475 60.2,88.475 61,89.275 61,95.26 BIAS.13@59.76,96.5
  Bottom Layer w0.25: v1(51.308,59.292) 51.308,59.258 52.045,58.522 52.662,58.522 52.853,58.331 sj15.1@52.853,57.912 sj19.1@52.853,57.25
VREFOUTAN: BIAS.14 sj15.2 UFE_4B1.15 | length 46.3
  Top Layer w0.1: UFE_4B1.15@52.8,58.075 51.85,58.075 49.1,60.825 49.1,82 55.8,88.7 59.225,88.7 59.76,89.235 BIAS.14@59.76,93.96
  Bottom Layer w0.2: v1(51.308,58.597) 51.993,57.912 sj15.2@52.303,57.912
  Bottom Layer w0.25: BIAS.14@59.325,93.525 BIAS.14@59.76,93.96
VREFOUTDIG: BIAS.26 sj21.2 UFE_4B1.21 | length 54.8
  Top Layer w0.1: v1(46.725,87.825) v1@46.75,87.8 ; 47.7,83.7 47.7,59.231 50.271,56.66 51.315,56.66 51.825,56.15 UFE_4B1.21@52.8,56.15
  Top Layer w0.25: v1@46.75,87.8 47.175,87.375 47.175,84.225 47.7,83.7
  Bottom Layer w0.3: sj21.2@35.4,86.525 36.275,86.525 36.9,85.9 40.425,85.9 42.35,87.825 v1@46.675,87.825 ; BIAS.26@44.52,93.96 46.725,91.755 v1(46.725,87.825)
VTHEXT: BIAS.24 VTH_EXT.2 | length 7
  Bottom Layer w0.25: BIAS.24@47.06,93.96 48.398,92.622 48.398,89.023 47.725,88.35 VTH_EXT.2@47.725,87.8
VTHINC: C55.1 R4.1 UFE_4B1.20 VTH_EXT.1 | length 39.4
  Top Layer w0.1: v1@51.7,87.5 51.7,86.8 47.9,83 47.9,59.3 50.35,56.85 51.394,56.85 51.819,56.425 UFE_4B1.20@52.8,56.425
  Bottom Layer w0.1: R4.1@50.5,87.75 R4.1@50.5,87.85
  Bottom Layer w0.3: VTH_EXT.1@48.275,87.8 48.325,87.75 R4.1@50.5,87.75 ; R4.1@50.55,87.8 C55.1@51.7,87.8
  other v1: 51.7,87.4
pads on no net: "Relay V3.3.7" "Relay V3.3.8" "Relay V3.3.9" "Relay V3.3.10" BIAS.4 BIAS.23 CON1.2 CON1.6 CON1.14 CON1.81 CON1.82 IC1.6 IC1.7 IC1.9 IC1.10 IC1.11 IC1.12 IC1.13 LVDS.MH3 LVDS.MH4 PWR.3 PWR.5 PWR.6 PWR.9 PWR.10
copper on no net: | length 611.9
  pad layer w0.01: 52.8,39.875 58.327,40.281
  pad layer w0.02: 52.775,45.425 58,46.712 ; 52.8,40.15 58,40.45 ; 52.8,40.45 58.327,40.664 ; 52.8,40.725 58,41.5 ; 52.8,41 58,41.65 ; 52.8,41.275 58,41.8 ; 52.8,41.55 58,41.95 ; 52.8,41.825 58,42.1 ; 52.8,42.1 58,42.25 ; 52.8,42.675 58,43.3 ; 52.8,42.95 58,43.45 ; 52.8,43.225 58,43.588 ; 52.8,43.5 58,43.688 ; 52.8,43.775 58,43.788 ; 52.8,44.05 58,45.125 ; 52.8,44.325 58,45.725 ; 52.8,44.6 58,45.875 ; 52.8,44.875 58,46.025 ; 52.8,45.15 58,46.612 ; 52.8,45.7 58,47.15 ; 52.8,45.975 58,47.3 ; 52.8,46.25 58,47.45 ; 52.8,46.5 58,47.6 ; 52.8,46.8 58,47.75 ; 52.8,47.075 58,47.9 ; 52.8,47.35 58,48.05 ; 52.8,47.625 58,48.2 ; 52.8,47.9 58,48.65 ; 52.8,48.175 58,48.8 ; 52.8,48.45 58,48.95 ; 52.8,48.725 58,49.1 ; 52.8,49.275 58,49.85 ; 52.8,49.55 58,50 ; 52.8,49.825 58,50.15 ; 52.8,50.1 58,50.3 ; 52.8,50.375 58,50.45 ; 52.8,50.65 58,50.6 ; 52.8,50.925 58,50.75 ; 52.8,51.2 58,50.9 ; 52.8,51.75 58,51.175 ; 52.8,52.025 58,51.325 ; 52.8,52.3 58,51.475 ; 52.8,52.575 58,51.925 ; 52.8,52.85 58,52.975 ; 52.8,53.125 58,53.425 ; 52.8,53.4 58,53.575 ; 52.8,53.675 58,53.725 ; 52.8,53.95 58,53.875 ; 52.8,54.5 58,54.475 ; 52.8,54.775 58,54.625 ; 52.8,55.05 58,55.225 ; 52.8,55.325 58,56.275 ; 52.8,55.6 52.775,55.575 58,56.425 ; 52.8,55.875 58,56.575 ; 52.8,56.15 58,57.633 ; 52.8,56.425 58,57.783 ; 52.8,56.7 58,57.933 ; 52.8,56.975 58,58.083 ; 52.8,57.25 58,58.233 ; 52.8,57.525 58,58.383 ; 52.8,57.8 58.298,58.46 ; 52.8,58.075 58,58.533 ; 52.8,58.35 58.298,58.61 ; 52.8,58.625 58,58.67 ; 52.8,58.9 58,58.77 ; 52.8,59.175 58.298,58.76 ; 52.8,59.45 58,58.87 ; 52.8,59.725 58,58.97 ; 52.8,60 58.298,58.91 ; 52.8,60.275 58,59.07 ; 52.8,60.55 58,59.17 ; 52.8,60.825 58,59.27 ; 52.8,61.1 58,59.37 ; 52.8,61.375 58,59.47 ; 52.8,61.65 58,59.57 ; 52.8,61.925 58,59.67 ; 52.8,62.2 58,59.77 ; 52.8,62.475 58,59.87 ; 52.8,62.75 58,60 ; 52.8,63.025 58.327,59.941 ; 52.8,63.3 58.327,60.169 ; 52.825,51.475 58,51.037 ; 54.675,40.914 58,40.9 ; 54.675,44.801 58,45.575 ; 54.675,46.172 58,47 ; 54.675,48.125 58,48.5 ; 54.675,49.45 58,49.7 ; 54.675,52.125 58,51.775 ; 54.675,52.423 58,52.375 ; 54.675,54.261 58,54.325 ; 54.675,55.605 58,55.525 ; 54.675,56.525 58,57.025 ; 54.7,49.175 58,49.4 ; 55.25,40.425 58,40.6 ; 55.25,40.775 58,40.75 ; 55.425,44.025 58,44.075 ; 55.425,46.325 58,46.85 ; 55.425,48.1 58,48.35 ; 55.425,49.075 58,49.25 ; 55.425,49.375 58,49.55 ; 55.425,51.975 58,51.625 ; 55.425,53.125 58,53.125 ; 55.425,54.05 58,54.025 ; 55.425,54.95 58,54.775 ; 55.425,55.813 55.426,55.813 ; 55.425,57.875 58.298,58.31 ; 55.65,41.05 58,41.05 ; 56.2,43.875 58,43.925 ; 56.2,44.225 58,44.225 ; 56.2,45.925 58,46.175 ; 56.2,52.575 58,52.525 ; 56.2,53.225 58,53.275 ; 56.2,54.175 58,54.175 ; 56.2,55.725 56.2,55.675 58,55.675 ; 56.2,55.825 58,55.975 ; 56.2,57 58,57.175 ; 58,41.2 55.25,41.092 58,41.35 ; 58,44.375 55.425,44.45 ; 58,44.525 55.425,44.45 ; 58,44.675 54.675,44.388 58,44.975 ; 58,44.825 55.425,44.45 ; 58,45.275 56.456,45.05 55.425,44.9 58,45.425 ; 58,46.325 55.425,45.875 58,46.475 ; 58,52.075 55.425,52.35 58,52.225 ; 58,52.675 55.425,52.775 58,52.825 ; 58,54.925 56.2,55.125 58,55.075 ; 58,55.375 55.425,55.825 55.522,55.825 ; 58,55.825 55.522,55.825 ; 58,56.125 55.522,55.825 ; 58,56.725 55.425,56.6 58,56.875 ; 58,57.325 55.471,56.911 58,57.475
  pad layer w0.1: 54.675,42.682 58,42.775 ; 55.425,42.95 58,43.075 ; 55.425,62.225 58.298,59.135 ; 56.2,61.7 58.298,59.435 ; 56.325,42.4 58,42.475 ; 56.6,63.4 58.298,59.735
  other v4: 52.8,38.875 52.8,64.3

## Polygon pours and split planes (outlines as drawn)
GND on GND (split plane): 78.74,82.55 60.96,82.55 60.96,64.77 56.896,64.77 56.896,38.1 60.96,38.1 60.96,0.51 0.51,0.51 0.51,99.49 78.74,99.49
REG1IN on power (split plane): 54.873,62.525 54.881,62.486 54.903,62.453 54.936,62.431 54.975,62.423 56.896,62.423 56.896,38.1 60.96,38.1 60.96,0.61 28.952,0.61 28.952,59.5 28.944,59.539 28.922,59.572 28.889,59.594 28.85,59.602 10.525,59.602 10.525,68.873 54.873,68.873
REG2IN on power (split plane): 78.74,82.55 60.96,82.55 60.96,64.77 56.896,64.77 56.896,62.627 55.077,62.627 55.077,68.975 55.069,69.014 55.047,69.047 55.014,69.069 54.975,69.077 10.423,69.077 10.384,69.069 10.351,69.047 10.329,69.014 10.322,68.975 10.322,59.5 10.329,59.461 10.351,59.428 10.384,59.406 10.423,59.398 28.748,59.398 28.748,0.51 0.51,0.51 0.51,99.49 78.74,99.49

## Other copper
Top Layer:
  rectangle net SENSOR: 77.7,35.6 78.8,37.1
  rectangle net GND: 19.45,53.8 22.475,55.07
  rectangle net GND: 19.35,58.885 22.375,60.155
  text "58/60" at 59.7,58.3 h2
  text "STFC FE-I4B SCC V1.5" at 65.808,5.034 h2
  text "NOV 2015" at 65.808,3.384 h2
GND (plane layer: these items are gaps in the copper):
  pour cut-out: 56.896,38.1 60.96,38.1 60.96,-0.254 100.33,-0.254 100.35,38.275 100.35,64.875 100.33,100.33 78.74,100.33 78.74,82.55 60.96,82.55 60.96,64.77 56.896,64.77
  pour cut-out: 37.63,4.8 40.13,4.8 40.13,2.3 37.63,2.3
  pour cut-out: 31.8,7 34.3,7 34.3,4.5 31.8,4.5
  pour cut-out: 37,10.45 41,10.45 41,6.35 37,6.35
power (plane layer: these items are gaps in the copper):
  pour cut-out: 56.896,38.1 60.96,38.1 60.96,-0.254 100.33,-0.254 100.35,38.275 100.35,64.875 100.33,100.33 78.74,100.33 78.74,82.55 60.96,82.55 60.96,64.77 56.896,64.77
  pour cut-out: 31.8,7.025 34.3,7.025 34.3,4.525 31.8,4.525
  pour cut-out: 37.63,4.825 40.13,4.825 40.13,2.325 37.63,2.325
  pour cut-out: 36.975,10.425 40.975,10.425 40.975,6.325 36.975,6.325
  lines w0.2: 10.423,59.5 28.85,59.5 28.85,0.508 99.1,0.508 99.1,62.525 54.975,62.525 54.975,68.975 10.423,68.975 10.423,59.5

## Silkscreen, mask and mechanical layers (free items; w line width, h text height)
Top Overlay:
  circle w0.254: c85.215,88.925 r0.5
  circle w0.254: c82.715,88.925 r0.5
  circle w0.254: c80.175,88.925 r0.5
  circle w0.254: c80.175,85.7 r0.5
  circle w0.254: c82.715,85.7 r0.5
  circle w0.254: c85.215,85.65 r0.5
  circle w0.254: c80.2,82.425 r0.5
  circle w0.254: c82.74,82.425 r0.5
  circle w0.254: c85.24,82.375 r0.5
  rectangle: 79.3,84.75 83.5,86.55
  rectangle: 81.925,81.45 86.125,83.25
  lines w0.127: 15.525,88.7 16.9,90.075
  lines w0.2: 67.5,29.675 67.5,33.575 ; 67.5,30.875 87.5,30.875 ; 87.5,29.7 87.5,33.6 ; 87.5,33.575 91.5,33.575 ; 87.5,69.575 91.5,69.575 ; 90.25,33.575 90.25,69.575
  lines w0.254: 78.865,84.45 78.865,86.92 86.465,86.92 86.465,84.41 78.905,84.41 ; 78.865,87.725 78.865,90.195 86.465,90.195 86.465,87.685 78.905,87.685 ; 78.89,81.175 78.89,83.645 86.49,83.645 86.49,81.135 78.93,81.135 ; 78.35,76.725 78.35,91.3 98.275,91.3 98.275,76.725 78.35,76.725
  text "OFF" at 87.3,88.275 h1
  text "ON" at 87.35,85 h1
  text "I2C Control" at 87.15,82.25 h1
  text "Iref on" at 79.45,79.1 h1
  text "V3.3 on" at 79.4,77.425 h1
  text "36.0mm" at 92.825,48.5 h1.52 r90
  text "Connect the UV Pads with" at 79,41.5 h2 r90
  text "flying wire" at 80.875,41.45 h2 r90
  text "20.0mm" at 73.35,28.65 h1.52
Top Solder:
  rectangle: 52.15,35.975 57.15,65.5
  rectangle: 53.371,39.268 54.571,63.318
  rectangle: 77.663,35.6 78.838,37.1
Mechanical 1:
  lines w0.1: 0,0 22.2,0 100,0 100,100 0,100 0,0
Mechanical 2:
  lines w0.6: 57.3,45.648 57.3,38.7 62.45,38.7 ; 57.3,47.1 57.3,51.15 ; 57.3,52.6 57.3,56.65 ; 57.3,58.302 57.3,64.45 62.45,64.45 ; 64.2,64.45 70.6,64.45 ; 64.3,38.7 70.7,38.7 ; 72.2,64.45 78.6,64.45 ; 72.3,38.7 78.7,38.7 ; 80.2,64.45 86.6,64.45 ; 80.3,38.7 86.7,38.7 ; 88.2,64.45 94.6,64.45 ; 88.3,38.7 94.7,38.7 ; 96.2,64.45 100,64.45 100,58.302 ; 96.3,38.7 100,38.7 100,45.648 ; 100,47.1 100,51.15 ; 100,52.6 100,56.65
Mechanical 28:
  circle w0.013: c65,79.575 r1.5
  circle w0.013: c65,79.575 r1.25
  circle w0.013: c95,79.575 r1.5
  circle w0.013: c95,79.575 r1.25
  circle w0.013: c65,23.575 r1.5
  circle w0.013: c65,23.575 r1.25
  circle w0.013: c95,23.575 r1.5
  circle w0.013: c95,23.575 r1.25
  circle w0.013: c95,5 r1.5
  circle w0.013: c95,5 r1.25
  circle w0.013: c5,5 r1.5
  circle w0.013: c5,5 r1.25
  circle w0.013: c5,95 r1.5
  circle w0.013: c5,95 r1.25
  circle w0.013: c95,95 r1.5
  circle w0.013: c95,95 r1.25
  circle w0.013: c87.5,69.575 r2.25
  circle w0.013: c67.5,69.575 r2.25
  circle w0.013: c67.5,33.575 r2.25
  circle w0.013: c87.5,33.575 r2.25
  circle w0.013: c106,-6 r4.48
  circle w0.013: c106,-6 r2.25
  circle w0.013: c-6,106 r4.48
  circle w0.013: c-6,106 r2.25
  circle w0.013: c106,106 r4.48
  circle w0.013: c106,106 r2.25
  circle w0.013: c-6,-6 r4.48
  circle w0.013: c-6,-6 r2.25
  lines w0.013: 55.5,27.575 100,27.575 ; 55.5,75.575 100,75.575 ; -12,-12 -12,112 112,112 112,-12 -12,-12 ; 0,0 10,0 10,10 0,10 0,0 ; 0,90 0,100 10,100 10,90 0,90 ; 45,30 45,40 50,40 50,30 45,30 ; 45,50 50,50 50,75 45,75 45,50 ; 55.5,18.575 100,18.575 100,84.575 55.5,84.575 55.5,18.575 ; 90,0 90,10 100,10 100,0 90,0 ; 90,90 100,90 100,100 90,100 90,90

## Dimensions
95,79.575 to 95,23.575 on Top Overlay
65,23.575 to 95,23.575 on Top Overlay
